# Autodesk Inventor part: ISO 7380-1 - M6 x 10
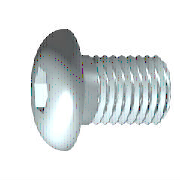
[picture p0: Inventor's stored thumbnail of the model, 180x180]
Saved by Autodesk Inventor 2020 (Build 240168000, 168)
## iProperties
Created: 2019-01
Part Number: ISO 7380-1 - M6 x 10
Material: Ocel
Description: Šrouby s půlkulovou hlavou s vnitřním šestihranem – výrobní třída A
Document SubType Name: Modeling
Standard: ISO 7380-1
Designer: doma
Standard Revision: First edition 2011-08-01
Standards Organization: ISO
Language: cs-CZ
Size Designation: M6 x 10
Categories: <MemberInstance><Categories><Category DisplayName="Spojovací materiál" InternalName="e4da775c-781d-43d5-af7c-5136215cf5a6" Mnemonic="FSTN"><Category DisplayName
Density: 7.85 g/cm^3
Appearance: Plech
IsCustomPart: 0
Author: doma
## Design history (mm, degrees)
sketch "Náčrt1"
  geometry: L1 (0.113, 0)-(10, 0); L2 (10, 0)-(10, 3); L3 (10, 3)-(3, 3); L4 (3, 3)-(2.386, 3); L5 (2.386, 3)-(0, 3); L6 (0, 3)-(0, 5.25); L7 (0, 5.25)-(-3.3, 5.25); L8 (-3.3, 5.25)-(-3.3, 2.309); L9 (-3.3, 2.309)-(-1.22, 2.309); L10 (-1.22, 2.309)-(0.113, 0); L11 (-5.96, 0)-(12.66, 0) reference; L12 (0, -1.05)-(0, 6.3) reference; L13 (3, 3)-(0, 3)
  constraints: 22 end point, 6 parallel, 2 collinear, 2 perpendicular, 1 horizontal, 1 point on line
  dimensions: "d1" = 7 distance from line of L3.end L2 (= GEL); "d2" = 0.61355 distance of L4.end L3.end (computed from GAL); "d3" = 3.3 distance between parallel lines of L8 L6 (= KOH); "d4" = 2.08 distance of L8.end L9.end (= INTI); "d5" = 60 deg angle of L10 L1; "d6" = 6 diameter of L3 L1 (= GD); "d7" = 6 diameter of L5 L1 (= BDM); "d8" = 4.6188 diameter of L9 L1 (= 1.1547 x SW); "d9" = 10.5 diameter of L7 L1 (= KOD); "d26" = 10 distance between parallel lines of L12 L2 (= NLG)
revolve "Těleso" sketch "Náčrt1" stored, may be unused: angle "d10" = 90 deg
sketch "Náčrt2"
  geometry: L1 (0, -7.35)-(0, 7.35) reference; L2 (-7.35, 0)-(7.35, 0) reference; L3 (2.309, 0)-(1.155, -2); L4 (1.155, -2)-(-1.155, -2); L5 (-1.155, -2)-(-2.309, 0); L6 (-2.309, 0)-(-1.155, 2); L7 (-1.155, 2)-(1.155, 2); L8 (1.155, 2)-(2.309, 0); 2 further points
  constraints: 12 end point, 1 coincident, 1 horizontal alignment, 1 point on line, 12 other
extrude "Drážka" join sketch "Náčrt2" stored distance "d11" = 10; taper "d12" = 0 deg
workplane "Work Plane1"
body "Solid1"
fillet "Zaoblení1" dims "d17" = 2.56 (= RR)
feature "Závit" dims "d13" = 7 (= GEL), "d14" = 0
chamfer "Zkosení1" distance "d15" = 0.61345 (= -0.5 x SPD + 0.5 x GD); stored, may be unused: second distance "d16" = 0.61345 (= GUL), angle "d27" = 45 deg
fillet "Zaoblení2" dims "d30" = 0.5 (= R)
other parameters: "GD" = 6 (= NND) [user parameter; used in 2 equation terms], "NLG" = 10 [user parameter; used in 1 equation term], "GEL" = 7 [user parameter; used in 2 equation terms], "KOD" = 10.5 [user parameter; used in 1 equation term], "KOH" = 3.3 [user parameter; used in 1 equation term], "INTI" = 2.08 [user parameter; used in 1 equation term], "GAL" = 0.61345 (= 0.61345 x PTC) [user parameter; used in 1 equation term], "GUL" = 0.61345 (= 0.61345 x PTC) [user parameter; used in 1 equation term], "BDM" = 6 (= NND) [user parameter; used in 1 equation term], "SW" = 4 [user parameter; used in 1 equation term], "RR" = 2.56 [user parameter; used in 1 equation term], "SPD" = 4.7731 (= NND - 1.2269 x PTC) [user parameter; used in 1 equation term], "d19" = 0, "d28" = 0, "d29" = 0, "R" = 0.5 [user parameter; used in 1 equation term], "TOA" = 30 deg [user parameter], "GD1" = 4.7731 (= THREADDIA - 1.2269 x PTC) [user parameter], "THREADDIA" = 6 [user parameter; used in 1 equation term], "PTC" = 1 [user parameter; used in 5 equation terms], "NND" = 6 [user parameter; used in 3 equation terms], "KOH1" = 0.74 [user parameter], "E0" = 4.583 [user parameter]
